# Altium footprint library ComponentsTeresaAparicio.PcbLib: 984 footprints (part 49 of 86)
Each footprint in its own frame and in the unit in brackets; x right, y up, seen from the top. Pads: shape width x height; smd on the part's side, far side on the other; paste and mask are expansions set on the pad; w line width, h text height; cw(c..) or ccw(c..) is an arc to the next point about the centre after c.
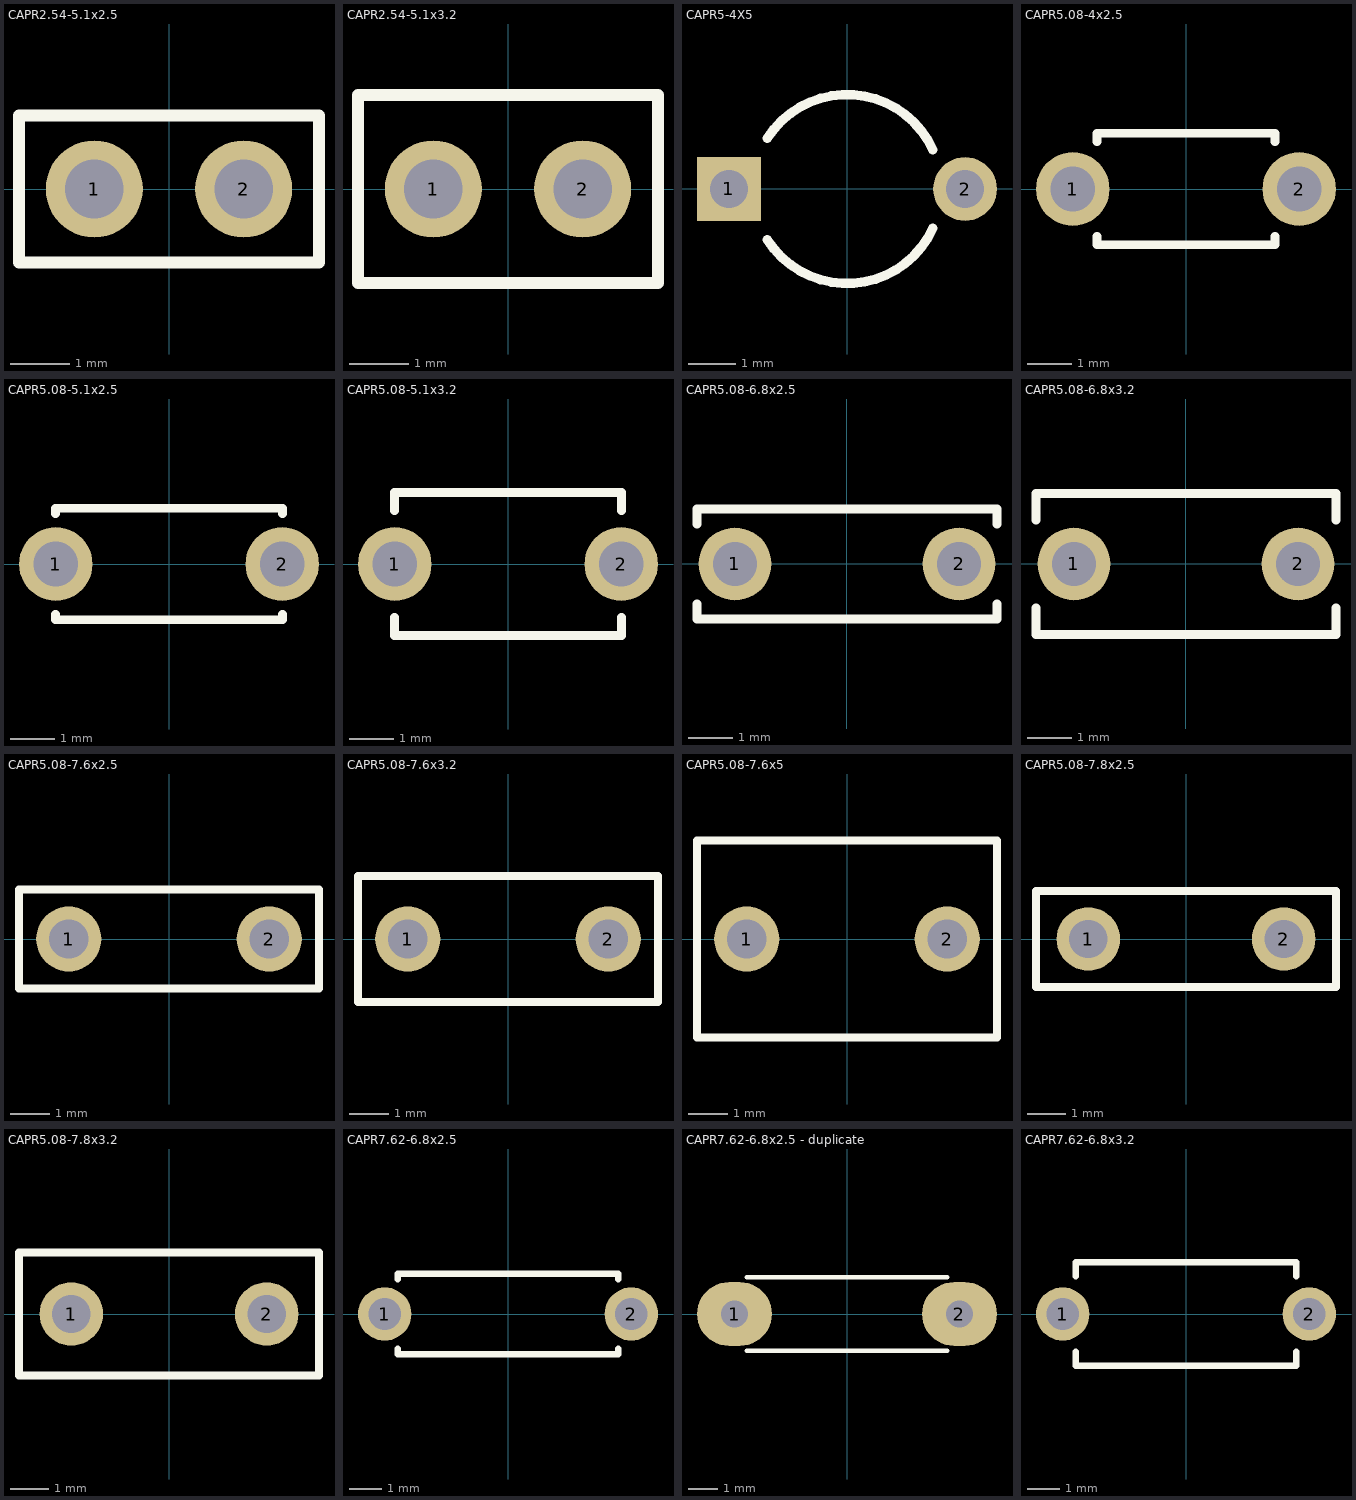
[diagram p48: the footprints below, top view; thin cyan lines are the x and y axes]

## CAPR2.54-5.1x2.5 [mm] "Capacitor, Ceramic, Thru-Hole, Dipped Radial; Body 5.1 x 2.5 mm (WxT) Pin Spacing 2.54 mm (typ)"
height 6
pads (2):
  round 1.65 hole 1: 1(-1.27,0) 2(1.27,0)
Top Overlay:
  lines w0.2: -2.55,-1.25 -2.55,1.25 2.55,1.25 2.55,-1.25 -2.55,-1.25

## CAPR2.54-5.1x3.2 [mm] "Capacitor, Ceramic, Thru-Hole, Dipped Radial; Body 5.1 x 3.2 mm (WxT) Pin Spacing 2.54 mm (typ)"
height 6
pads (2):
  round 1.65 hole 1: 1(-1.27,0) 2(1.27,0)
Top Overlay:
  lines w0.2: -2.55,-1.6 -2.55,1.6 2.55,1.6 2.55,-1.6 -2.55,-1.6

## CAPR5-4X5 [mm] "Capacitor; 2 Leads"
height 12
pads (2):
  rect 1.35x1.35 hole 0.8: 1(-2.5,0)
  round 1.35 hole 0.8: 2(2.5,0)
Top Overlay:
  lines w0.2: -1.687,-1.075 ccw(c0,0) 1.819,-0.832 ; -1.687,1.075 cw(c0,0) 1.819,0.832

## CAPR5.08-4x2.5 [mm] "Capacitor, Ceramic, Thru-Hole, Dipped Radial; Body 4 x 2.5 mm (WxT) Pin Spacing 5.08 mm (typ)"
height 4.6
pads (2):
  round 1.65 hole 1: 1(-2.54,0) 2(2.54,0)
Top Overlay:
  lines w0.2: -2,-1.07 -2,-1.25 2,-1.25 2,-1.07 ; -2,1.07 -2,1.25 2,1.25 2,1.07

## CAPR5.08-5.1x2.5 [mm] "Capacitor, Ceramic, Thru-Hole, Dipped Radial; Body 5.1 x 2.5 mm (WxT) Pin Spacing 5.08 mm (typ)"
height 6
pads (2):
  round 1.65 hole 1: 1(-2.54,0) 2(2.54,0)
Top Overlay:
  lines w0.2: -2.55,-1.13 -2.55,-1.25 2.55,-1.25 2.55,-1.13 ; -2.55,1.13 -2.55,1.25 2.55,1.25 2.55,1.13

## CAPR5.08-5.1x3.2 [mm] "Capacitor, Ceramic, Thru-Hole, Dipped Radial; Body 5.1 x 3.2 mm (WxT) Pin Spacing 5.08 mm (typ)"
height 6
pads (2):
  round 1.65 hole 1: 1(-2.54,0) 2(2.54,0)
Top Overlay:
  lines w0.2: -2.55,-1.2 -2.55,-1.6 2.55,-1.6 2.55,-1.2 ; -2.55,1.2 -2.55,1.6 2.55,1.6 2.55,1.2

## CAPR5.08-6.8x2.5 [mm] "Capacitor, Ceramic, Thru-Hole, Dipped Radial; Body 6.8 x 2.5 mm (WxT) Pin Spacing 5.08 mm (typ)"
height 7
pads (2):
  round 1.65 hole 1: 1(-2.54,0) 2(2.54,0)
Top Overlay:
  lines w0.2: -3.4,-0.91 -3.4,-1.25 3.4,-1.25 3.4,-0.91 ; -3.4,0.91 -3.4,1.25 3.4,1.25 3.4,0.91

## CAPR5.08-6.8x3.2 [mm] "Capacitor, Ceramic, Thru-Hole, Dipped Radial; Body 6.8 x 3.2 mm (WxT) Pin Spacing 5.08 mm (typ)"
height 7
pads (2):
  round 1.65 hole 1: 1(-2.54,0) 2(2.54,0)
Top Overlay:
  lines w0.2: -3.4,-1 -3.4,-1.6 3.4,-1.6 3.4,-1 ; -3.4,1 -3.4,1.6 3.4,1.6 3.4,1

## CAPR5.08-7.6x2.5 [mm] "Capacitor, Ceramic, Thru-Hole, Dipped Radial; Body 7.6 x 2.5 mm (WxT) Pin Spacing 5.08 mm (typ)"
height 9
pads (2):
  round 1.65 hole 1: 1(-2.54,0) 2(2.54,0)
Top Overlay:
  lines w0.2: -3.8,-1.25 3.8,-1.25 3.8,1.25 -3.8,1.25 -3.8,-1.25

## CAPR5.08-7.6x3.2 [mm] "Capacitor, Ceramic, Thru-Hole, Dipped Radial; Body 7.6 x 3.2 mm (WxT) Pin Spacing 5.08 mm (typ)"
height 9
pads (2):
  round 1.65 hole 1: 1(-2.54,0) 2(2.54,0)
Top Overlay:
  lines w0.2: -3.8,-1.6 -3.8,1.6 3.8,1.6 3.8,-1.6 -3.8,-1.6

## CAPR5.08-7.6x5 [mm] "Capacitor, Ceramic, Thru-Hole, Dipped Radial; Body 7.6 x 5 mm (WxT) Pin Spacing 5.08 mm (typ)"
height 9
pads (2):
  round 1.65 hole 1: 1(-2.54,0) 2(2.54,0)
Top Overlay:
  lines w0.2: -3.8,-2.5 -3.8,2.5 3.8,2.5 3.8,-2.5 -3.8,-2.5

## CAPR5.08-7.8x2.5 [mm] "Capacitor, Ceramic, Thru-Hole, Dipped Radial; Body 7.8 x 2.5 mm (WxT) Pin Spacing 5.08 mm (typ)"
height 10
pads (2):
  round 1.65 hole 1: 1(-2.54,0) 2(2.54,0)
Top Overlay:
  lines w0.2: -3.9,-1.25 -3.9,1.25 3.9,1.25 3.9,-1.25 -3.9,-1.25

## CAPR5.08-7.8x3.2 [mm] "Capacitor, Ceramic, Thru-Hole, Dipped Radial; Body 7.8 x 3.2 mm (WxT) Pin Spacing 5.08 mm (typ)"
height 10
pads (2):
  round 1.65 hole 1: 1(-2.54,0) 2(2.54,0)
Top Overlay:
  lines w0.2: -3.9,-1.6 -3.9,1.6 3.9,1.6 3.9,-1.6 -3.9,-1.6

## CAPR7.62-6.8x2.5 [mm] "Capacitor, Ceramic, Thru-Hole, Dipped Radial; Body 6.8 x 2.5 mm (WxT) Pin Spacing 7.62 mm (typ)"
height 6
pads (2):
  round 1.65 hole 1: 1(-3.81,0) 2(3.81,0)
Top Overlay:
  lines w0.2: -3.4,-1.08 -3.4,-1.25 3.4,-1.25 3.4,-1.08 ; -3.4,1.08 -3.4,1.25 3.4,1.25 3.4,1.08

## CAPR7.62-6.8x2.5 - duplicate [mil] "Capacitor, MF, Thru-Hole, Dipped Radial; Body 6.8 x 2.5 mm (WxT) Pin Spacing 7.62 mm (typ)"
height 236.22
pads (2):
  oval 100x85 hole 36 unplated: 1(-150,0) 2(150,0)
Top Overlay:
  lines w6: -133.86,-49.21 133.86,-49.21 ; -133.86,49.21 133.86,49.21
3D body: height 511.81, standoff -100, extent -202.75,-118.1 202.76,118.12

## CAPR7.62-6.8x3.2 [mm] "Capacitor, Ceramic, Thru-Hole, Dipped Radial; Body 6.8 x 3.2 mm (WxT) Pin Spacing 7.62 mm (typ)"
height 6
pads (2):
  round 1.65 hole 1: 1(-3.81,0) 2(3.81,0)
Top Overlay:
  lines w0.2: -3.4,-1.17 -3.4,-1.6 3.4,-1.6 3.4,-1.17 ; -3.4,1.17 -3.4,1.6 3.4,1.6 3.4,1.17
